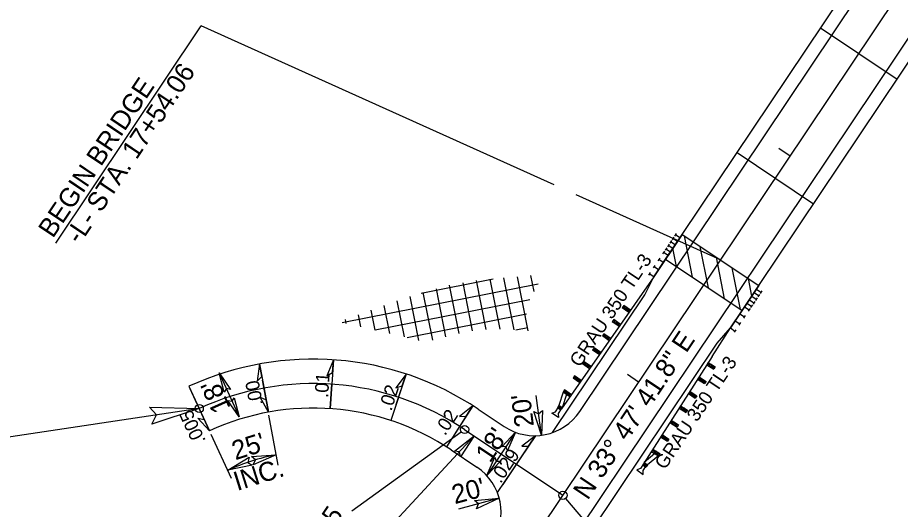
# Model space of a CAD drawing. Extents: x 1716813 to 1718091, y 800228 to 801730.
# Drawn here: x 1717290.1 to 1717614.3, y 800961.6 to 801142.3 of the extents above; entities that cross this region are included whole.
import ezdxf

# ---------------------------------------------------------------- set-up
doc = ezdxf.new("R2010")
doc.units = 0
for name, color, linetype in [('Prop Approach Slab', 7, 'Continuous'), ('Prop Dimension', 7, 'Continuous'), ('Prop Dimension Text', 7, 'Continuous'), ('Prop EOT', 7, 'Continuous'), ('Prop Guardrail', 7, 'Continuous'), ('Prop Guardrail Anchor Unit CELL', 7, 'Continuous'), ('Prop Horizontal Alignment', 7, 'Continuous'), ('Prop Horizontal Alignment Direction Label', 7, 'Continuous'), ('Prop Horizontal Alignment Station Label', 7, 'Continuous'), ('Prop Horizontal Alignment Tick Large', 7, 'Continuous'), ('Prop Horizontal Alignment Tick Small', 7, 'Continuous'), ('Prop Paved Shoulder', 7, 'Continuous'), ('Prop Rem of Exist Asph Pvmt', 7, 'Continuous'), ('Prop Roadway Bridge', 7, 'Continuous'), ('Prop Structure Anchor Unit CELL', 7, 'Continuous'), ('Prop Superelevation  Arrow CELL', 7, 'Continuous'), ('Prop Superelevation Label', 7, 'Continuous'), ('Prop Terminator CELL', 7, 'Continuous')]:
    doc.layers.add(name, color=color, linetype=linetype)

msp = doc.modelspace()

# ---------------------------------------------------------------- linework, layer by layer
at = {"layer": 'Prop Approach Slab'}
for p, q in [((1717528.05, 801053.5), (1717534.16, 801062.64)), ((1717537.95, 801046.87), (1717534.93, 801062.13)), ((1717532.07, 801050.81), (1717530.74, 801057.53)), ((1717543.82, 801042.94), (1717540.8, 801058.2)), ((1717528.05, 801053.5), (1717556.16, 801034.68)), ((1717549.7, 801039.01), (1717546.68, 801054.27)), ((1717555.58, 801035.08), (1717552.55, 801050.33)), ((1717559.7, 801039.98), (1717558.43, 801046.4)), ((1717556.16, 801034.68), (1717562.28, 801043.83))]:
    msp.add_line(p, q, dxfattribs=at)
at = {"layer": 'Prop Dimension'}
for p, q in [((1717364.14, 801011.72), (1717371.42, 800995.53)), ((1717482.44, 800988.82), (1717480.56, 801003.42)), ((1717385.77, 800977.82), (1717382.4, 800996.16)), ((1717368.63, 800972.93), (1717361.2, 800989.06)), ((1717472.9, 800989.91), (1717462.35, 800973.99)), ((1717466.92, 800965.68), (1717452.01, 800961.65))]:
    msp.add_line(p, q, dxfattribs=at)
msp.add_arc((1717398.63, 800907.81), 75, 100.4104, 114.7344, dxfattribs=at)
at = {"layer": 'Prop Dimension Text'}
for p, q in [((1717304.11, 801059.4), (1717357.55, 801139.24)), ((1717487.11, 801080.8), (1717357.55, 801139.24)), ((1717548.22, 801053.23), (1717495.17, 801077.16))]:
    msp.add_line(p, q, dxfattribs=at)
at = {"layer": 'Prop EOT'}
for p, q in [((1717496.5, 800997.53), (1717644.84, 801219.17)), ((1717458.6, 800897.76), (1717664.79, 801205.82)), ((1717459.26, 800998.39), (1717468.75, 800992.04)), ((1717449.25, 800983.43), (1717458.74, 800977.08))]:
    msp.add_line(p, q, dxfattribs=at)
for centre, radius, start, end in [((1717398.63, 800907.81), 109, 56.2051, 114.7344), ((1717398.63, 800907.81), 91, 56.2051, 114.7344), ((1717479.88, 801008.66), 20, 236.2051, 326.2051), ((1717447.62, 800960.46), 20, 326.2051, 56.2051)]:
    msp.add_arc(centre, radius, start, end, dxfattribs=at)
at = {"layer": 'Prop Guardrail'}
for p, q in [((1717523.73, 801047.06), (1717516.58, 801036.82)), ((1717545.11, 801017.72), (1717551.85, 801028.24))]:
    msp.add_line(p, q, dxfattribs=at)
at = {"layer": 'Prop Guardrail Anchor Unit CELL'}
for p, q in [((1717516.58, 801036.82), (1717489.83, 800998.47)), ((1717512.66, 801036.45), (1717512.09, 801035.63)), ((1717514.55, 801033.91), (1717512.09, 801035.63)), ((1717512.09, 801035.63), (1717513.89, 801035.59)), ((1717515.12, 801034.73), (1717512.66, 801036.45)), ((1717513.32, 801034.77), (1717512.66, 801036.45)), ((1717513.89, 801035.59), (1717513.32, 801034.77)), ((1717514.55, 801033.91), (1717513.32, 801034.77)), ((1717513.32, 801034.77), (1717515.12, 801034.73)), ((1717513.89, 801035.59), (1717514.55, 801033.91)), ((1717515.12, 801034.73), (1717514.55, 801033.91)), ((1717509.01, 801031.31), (1717508.44, 801030.49)), ((1717510.94, 801028.74), (1717508.44, 801030.49)), ((1717508.44, 801030.49), (1717510.26, 801030.43)), ((1717511.52, 801029.56), (1717509.01, 801031.31)), ((1717509.69, 801029.61), (1717509.01, 801031.31)), ((1717510.26, 801030.43), (1717509.69, 801029.61)), ((1717510.26, 801030.43), (1717510.94, 801028.74)), ((1717511.52, 801029.56), (1717509.69, 801029.61)), ((1717505.41, 801026.14), (1717504.84, 801025.32)), ((1717507.34, 801023.57), (1717504.84, 801025.32)), ((1717504.84, 801025.32), (1717506.66, 801025.27)), ((1717507.91, 801024.39), (1717505.41, 801026.14)), ((1717506.09, 801024.44), (1717505.41, 801026.14)), ((1717506.66, 801025.27), (1717506.09, 801024.44)), ((1717507.91, 801024.39), (1717506.09, 801024.44)), ((1717506.66, 801025.27), (1717507.34, 801023.57)), ((1717501.82, 801020.96), (1717501.24, 801020.14)), ((1717504.31, 801019.23), (1717501.82, 801020.96)), ((1717502.49, 801019.27), (1717501.82, 801020.96)), ((1717503.73, 801018.4), (1717501.24, 801020.14)), ((1717501.24, 801020.14), (1717503.06, 801020.09)), ((1717503.06, 801020.09), (1717502.49, 801019.27)), ((1717504.31, 801019.23), (1717502.49, 801019.27)), ((1717503.06, 801020.09), (1717503.73, 801018.4)), ((1717504.31, 801019.23), (1717503.73, 801018.4)), ((1717545.11, 801017.72), (1717519.89, 800978.35)), ((1717498.13, 801015.85), (1717497.56, 801015.03)), ((1717500.13, 801013.24), (1717497.56, 801015.03)), ((1717497.56, 801015.03), (1717499.42, 801014.95)), ((1717500.7, 801014.06), (1717498.13, 801015.85)), ((1717498.84, 801014.13), (1717498.13, 801015.85)), ((1717499.42, 801014.95), (1717498.84, 801014.13)), ((1717500.7, 801014.06), (1717498.84, 801014.13)), ((1717499.42, 801014.95), (1717500.13, 801013.24)), ((1717543.74, 801015.58), (1717543.2, 801014.74)), ((1717545, 801014.77), (1717543.2, 801014.74)), ((1717543.2, 801014.74), (1717545.72, 801013.12)), ((1717543.2, 801014.74), (1717544.46, 801013.93)), ((1717543.74, 801015.58), (1717546.26, 801013.96)), ((1717544.46, 801013.93), (1717543.74, 801015.58)), ((1717545, 801014.77), (1717544.46, 801013.93)), ((1717544.46, 801013.93), (1717546.26, 801013.96)), ((1717545.72, 801013.12), (1717545, 801014.77)), ((1717546.26, 801013.96), (1717545.72, 801013.12)), ((1717494.64, 801010.6), (1717494.06, 801009.78)), ((1717496.52, 801008.07), (1717494.06, 801009.78)), ((1717494.06, 801009.78), (1717495.87, 801009.75)), ((1717497.1, 801008.89), (1717494.64, 801010.6)), ((1717495.29, 801008.93), (1717494.64, 801010.6)), ((1717495.87, 801009.75), (1717495.29, 801008.93)), ((1717497.1, 801008.89), (1717495.29, 801008.93)), ((1717495.87, 801009.75), (1717496.52, 801008.07)), ((1717541.62, 801009.45), (1717539.8, 801009.43)), ((1717539.8, 801009.43), (1717542.37, 801007.78)), ((1717540.34, 801010.27), (1717542.91, 801008.63)), ((1717540.34, 801010.27), (1717541.08, 801008.61)), ((1717541.62, 801009.45), (1717541.08, 801008.61)), ((1717541.08, 801008.61), (1717542.91, 801008.63)), ((1717542.37, 801007.78), (1717541.62, 801009.45)), ((1717542.91, 801008.63), (1717542.37, 801007.78)), ((1717490.41, 801004.65), (1717488.89, 800999.74)), ((1717490.98, 801005.47), (1717490.41, 801004.65)), ((1717492.92, 801002.9), (1717490.41, 801004.65)), ((1717490.41, 801004.65), (1717492.23, 801004.6)), ((1717493.49, 801003.72), (1717490.98, 801005.47)), ((1717491.66, 801003.78), (1717490.98, 801005.47)), ((1717492.23, 801004.6), (1717491.66, 801003.78)), ((1717492.23, 801004.6), (1717492.92, 801002.9)), ((1717536.94, 801004.97), (1717539.5, 801003.32)), ((1717536.94, 801004.97), (1717537.68, 801003.3)), ((1717491.66, 801003.78), (1717490.12, 800998.88)), ((1717493.49, 801003.72), (1717491.66, 801003.78)), ((1717538.22, 801004.14), (1717536.4, 801004.12)), ((1717536.4, 801004.12), (1717538.96, 801002.48)), ((1717538.22, 801004.14), (1717537.68, 801003.3)), ((1717537.68, 801003.3), (1717539.5, 801003.32)), ((1717538.96, 801002.48), (1717538.22, 801004.14)), ((1717539.5, 801003.32), (1717538.96, 801002.48)), ((1717487.59, 800997.47), (1717488.74, 800999.17)), ((1717488.89, 800999.74), (1717488.31, 800998.92)), ((1717489.54, 800998.06), (1717488.31, 800998.92)), ((1717488.31, 800998.92), (1717490.12, 800998.88)), ((1717488.89, 800999.74), (1717488.6, 800999.33)), ((1717489.75, 800998.49), (1717488.61, 800996.79)), ((1717488.74, 800999.17), (1717489.24, 800998.83)), ((1717490.12, 800998.88), (1717488.89, 800999.74)), ((1717489.54, 800998.06), (1717488.89, 800999.74)), ((1717489.24, 800998.83), (1717489.75, 800998.49)), ((1717533.54, 800999.66), (1717533, 800998.82)), ((1717534.82, 800998.84), (1717533, 800998.82)), ((1717533, 800998.82), (1717535.55, 800997.18)), ((1717533.54, 800999.66), (1717536.09, 800998.02)), ((1717533.54, 800999.66), (1717534.28, 800998)), ((1717534.82, 800998.84), (1717534.28, 800998)), ((1717534.28, 800998), (1717536.09, 800998.02)), ((1717535.55, 800997.18), (1717534.82, 800998.84)), ((1717536.09, 800998.02), (1717535.55, 800997.18)), ((1717486.23, 800996.97), (1717487.59, 800997.47)), ((1717488.67, 800995.33), (1717486.23, 800996.97)), ((1717488.61, 800996.79), (1717488.67, 800995.33)), ((1717529.6, 800993.51), (1717532.24, 800991.82)), ((1717531.46, 800993.51), (1717529.6, 800993.51)), ((1717530.14, 800994.36), (1717532.78, 800992.66)), ((1717530.14, 800994.36), (1717530.92, 800992.67)), ((1717531.46, 800993.51), (1717530.92, 800992.67)), ((1717530.92, 800992.67), (1717532.78, 800992.66)), ((1717532.24, 800991.82), (1717531.46, 800993.51)), ((1717532.78, 800992.66), (1717532.24, 800991.82)), ((1717528, 800988.24), (1717526.2, 800988.21)), ((1717526.2, 800988.21), (1717528.72, 800986.59)), ((1717526.74, 800989.05), (1717529.26, 800987.43)), ((1717526.74, 800989.05), (1717527.46, 800987.4)), ((1717528, 800988.24), (1717527.46, 800987.4)), ((1717528.72, 800986.59), (1717528, 800988.24)), ((1717527.46, 800987.4), (1717529.26, 800987.43)), ((1717529.26, 800987.43), (1717528.72, 800986.59)), ((1717524.09, 800982.07), (1717520.16, 800978.78)), ((1717524.63, 800982.92), (1717522.8, 800982.9)), ((1717522.8, 800982.9), (1717525.38, 800981.25)), ((1717523.34, 800983.74), (1717525.92, 800982.09)), ((1717523.34, 800983.74), (1717524.09, 800982.07)), ((1717524.63, 800982.92), (1717524.09, 800982.07)), ((1717524.09, 800982.07), (1717525.92, 800982.09)), ((1717525.38, 800981.25), (1717524.63, 800982.92)), ((1717525.92, 800982.09), (1717525.38, 800981.25)), ((1717519.93, 800978.29), (1717518.8, 800976.58)), ((1717520.44, 800977.95), (1717519.93, 800978.29)), ((1717520.16, 800978.78), (1717521.42, 800977.97)), ((1717520.88, 800977.12), (1717520.16, 800978.78)), ((1717525.38, 800981.25), (1717521.42, 800977.97)), ((1717518.8, 800976.58), (1717517.43, 800976.08)), ((1717517.43, 800976.08), (1717519.87, 800974.45)), ((1717519.62, 800977.93), (1717521.42, 800977.97)), ((1717519.62, 800977.93), (1717520.88, 800977.12)), ((1717519.81, 800975.91), (1717520.95, 800977.61)), ((1717519.87, 800974.45), (1717519.81, 800975.91)), ((1717520.95, 800977.61), (1717520.44, 800977.95)), ((1717521.42, 800977.97), (1717520.88, 800977.12)), ((1717521.42, 800977.97), (1717521.15, 800977.55))]:
    msp.add_line(p, q, dxfattribs=at)
at = {"layer": 'Prop Horizontal Alignment'}
for p, q in [((1717404.5, 800838.5), (1717654.82, 801212.49)), ((1717454.25, 800990.91), (1717490.34, 800966.76))]:
    msp.add_line(p, q, dxfattribs=at)
msp.add_arc((1717398.63, 800907.81), 100, 56.2051, 114.7344, dxfattribs=at)
at = {"layer": 'Prop Horizontal Alignment Direction Label'}
msp.add_line((1717401.02, 800927.49), (1717457.77, 800988.56), dxfattribs=at)
at = {"layer": 'Prop Horizontal Alignment Station Label'}
for p, q in [((1717355.3, 800998.42), (1717211.72, 800976.91)), ((1717412.87, 800961.04), (1717453.03, 800990.03)), ((1717491.31, 800965.62), (1717577.75, 800864.17))]:
    msp.add_line(p, q, dxfattribs=at)
for centre in [(1717356.79, 800998.64), (1717454.25, 800990.91), (1717490.34, 800966.76)]:
    msp.add_circle(centre, 1.5, dxfattribs=at)
at = {"layer": 'Prop Horizontal Alignment Tick Large'}
msp.add_line((1717356.79, 800998.64), (1717353.44, 801005.9), dxfattribs=at)
at = {"layer": 'Prop Horizontal Alignment Tick Small'}
for p, q in [((1717573.77, 801091.41), (1717569.62, 801094.19)), ((1717518.15, 801008.31), (1717514, 801011.09)), ((1717452.45, 800992.09), (1717455.14, 800996.31))]:
    msp.add_line(p, q, dxfattribs=at)
at = {"layer": 'Prop Paved Shoulder'}
for p, q in [((1717523.73, 801047.06), (1717528.05, 801053.5)), ((1717520.42, 801040.46), (1717523.73, 801047.06)), ((1717486.5, 800989.78), (1717520.42, 801040.46)), ((1717551.85, 801028.24), (1717556.16, 801034.68)), ((1717547.01, 801022.66), (1717551.85, 801028.24)), ((1717461.92, 800895.53), (1717547.01, 801022.66))]:
    msp.add_line(p, q, dxfattribs=at)
at = {"layer": 'Prop Rem of Exist Asph Pvmt'}
for p, q in [((1717472.38, 801027.57), (1717468.6, 801046.66)), ((1717477.54, 801027.23), (1717473.61, 801047.07)), ((1717479.77, 801041.71), (1717478.61, 801047.57)), ((1717409.32, 801030.23), (1717481.29, 801044.48)), ((1717438.29, 801041.06), (1717464.74, 801046.3)), ((1717452.25, 801026.27), (1717448.75, 801043.94)), ((1717457.17, 801027.16), (1717453.66, 801044.89)), ((1717462.15, 801027.74), (1717458.61, 801045.64)), ((1717467.24, 801027.76), (1717463.6, 801046.18)), ((1717442.55, 801023.77), (1717439.07, 801041.31)), ((1717447.4, 801025.02), (1717443.91, 801042.63)), ((1717421.42, 801027.52), (1717478.15, 801038.76)), ((1717432.11, 801024.99), (1717429.49, 801038.22)), ((1717437.48, 801023.62), (1717434.28, 801039.77)), ((1717421.43, 801027.44), (1717419.97, 801034.81)), ((1717426.77, 801026.21), (1717424.73, 801036.51)), ((1717433.15, 801024.75), (1717476.95, 801033.43)), ((1717410.75, 801029.9), (1717410.47, 801031.33)), ((1717416.09, 801028.67), (1717415.22, 801033.09)), ((1717472.99, 801027.55), (1717477.47, 801028.43))]:
    msp.add_line(p, q, dxfattribs=at)
at = {"layer": 'Prop Roadway Bridge'}
for p, q in [((1717534.16, 801062.64), (1717602.3, 801164.45)), ((1717562.28, 801043.83), (1717630.42, 801145.63)), ((1717584.96, 801138.53), (1717613.07, 801119.72)), ((1717554.29, 801092.72), (1717582.41, 801073.9)), ((1717534.16, 801062.64), (1717562.28, 801043.83))]:
    msp.add_line(p, q, dxfattribs=at)
at = {"layer": 'Prop Structure Anchor Unit CELL'}
for p, q in [((1717534.16, 801062.64), (1717523.73, 801047.06)), ((1717531.95, 801062.93), (1717531.31, 801061.98)), ((1717530.21, 801060.34), (1717529.58, 801059.39)), ((1717531.56, 801058.75), (1717529.89, 801059.86)), ((1717531.08, 801061.64), (1717530.44, 801060.68)), ((1717532.43, 801060.05), (1717530.76, 801061.16)), ((1717533.29, 801061.35), (1717531.63, 801062.46)), ((1717527.61, 801056.44), (1717526.97, 801055.49)), ((1717528.47, 801057.74), (1717527.84, 801056.79)), ((1717529.82, 801056.15), (1717528.16, 801057.26)), ((1717529.34, 801059.04), (1717528.71, 801058.09)), ((1717530.69, 801057.45), (1717529.03, 801058.56)), ((1717525.87, 801053.84), (1717525.23, 801052.89)), ((1717527.21, 801052.26), (1717525.55, 801053.37)), ((1717528.95, 801054.85), (1717527.29, 801055.97)), ((1717524.13, 801051.25), (1717523.49, 801050.3)), ((1717525.47, 801049.66), (1717523.81, 801050.77)), ((1717522.39, 801048.65), (1717521.75, 801047.7)), ((1717523.73, 801047.06), (1717522.07, 801048.17)), ((1717562.28, 801043.83), (1717551.85, 801028.24)), ((1717559.67, 801039.93), (1717561.34, 801038.82)), ((1717560.54, 801041.23), (1717562.2, 801040.12)), ((1717561.41, 801042.53), (1717563.07, 801041.41)), ((1717562.52, 801040.59), (1717561.89, 801039.64)), ((1717563.39, 801041.89), (1717562.75, 801040.94)), ((1717557.93, 801037.33), (1717559.6, 801036.22)), ((1717558.8, 801038.63), (1717560.47, 801037.52)), ((1717559.92, 801036.7), (1717559.28, 801035.74)), ((1717560.78, 801037.99), (1717560.15, 801037.04)), ((1717561.65, 801039.29), (1717561.02, 801038.34)), ((1717555.33, 801033.44), (1717556.99, 801032.32)), ((1717557.07, 801036.03), (1717558.73, 801034.92)), ((1717559.05, 801035.4), (1717558.41, 801034.45)), ((1717553.59, 801030.84), (1717555.25, 801029.73)), ((1717555.57, 801030.2), (1717554.93, 801029.25)), ((1717557.31, 801032.8), (1717556.67, 801031.85)), ((1717551.85, 801028.24), (1717553.51, 801027.13)), ((1717553.83, 801027.61), (1717553.19, 801026.65))]:
    msp.add_line(p, q, dxfattribs=at)
at = {"layer": 'Prop Superelevation  Arrow CELL'}
for p, q in [((1717378.93, 801015.02), (1717381.1, 801003.21)), ((1717406.07, 801016.56), (1717405.45, 801007.58)), ((1717432.74, 801011.33), (1717428.99, 800999.94)), ((1717382.19, 800997.31), (1717380.02, 801009.11)), ((1717404.84, 800998.6), (1717405.45, 801007.58)), ((1717360.55, 800990.46), (1717355.53, 801001.36)), ((1717457.29, 800999.68), (1717450.83, 800989.56)), ((1717480.24, 800988.66), (1717473.56, 800978.69)), ((1717478.24, 800985.68), (1717468.23, 800970.73))]:
    msp.add_line(p, q, dxfattribs=at)
for points in [[(1717378.93, 801015.02), (1717378.05, 801008.75), (1717379.77, 801010.47)], [(1717406.07, 801016.56), (1717403.66, 801010.71), (1717405.75, 801011.94)], [(1717432.74, 801011.33), (1717428.96, 801006.26), (1717431.29, 801006.94)], [(1717382.19, 800997.31), (1717379.13, 801002.85), (1717381.35, 801001.86)], [(1717457.29, 800999.68), (1717452.38, 800995.7), (1717454.8, 800995.78)], [(1717360.55, 800990.46), (1717356.23, 800995.07), (1717358.62, 800994.66)], [(1717480.24, 800988.66), (1717475.24, 800984.79), (1717477.66, 800984.82)]]:
    msp.add_lwpolyline(points, close=True, dxfattribs=at)
at = {"layer": 'Prop Superelevation Label'}
for p, q in [((1717378.93, 801015.02), (1717382.19, 800997.31)), ((1717432.74, 801011.33), (1717427.11, 800994.24)), ((1717405.45, 801007.58), (1717404.84, 800998.6)), ((1717353.02, 801006.81), (1717360.55, 800990.46)), ((1717457.29, 800999.68), (1717447.61, 800984.51)), ((1717360.55, 800990.46), (1717360.55, 800990.46)), ((1717480.24, 800988.66), (1717466.24, 800967.75))]:
    msp.add_line(p, q, dxfattribs=at)
at = {"layer": 'Prop Terminator CELL'}
for points in [[(1717365.97, 801004.64), (1717364.14, 801011.72), (1717368.28, 801005.64), (1717366.74, 801005.95)], [(1717369.6, 801002.61), (1717371.42, 800995.53), (1717367.29, 801001.61), (1717368.83, 801001.3)], [(1717338.53, 800999.12), (1717356.79, 800998.64), (1717339.34, 800992.87), (1717341.15, 800996.36)], [(1717482.83, 800997.95), (1717482.44, 800988.82), (1717479.7, 800997.59), (1717481.43, 800996.66)], [(1717450.51, 800983.02), (1717457.77, 800988.56), (1717452.78, 800980.84), (1717452.39, 800982.77)], [(1717467.89, 800984.6), (1717472.9, 800989.91), (1717469.97, 800983.17), (1717469.41, 800984.65)], [(1717375.96, 800980.98), (1717385.08, 800981.58), (1717376.65, 800977.91), (1717377.39, 800979.73)], [(1717376.19, 800977.81), (1717367.25, 800975.93), (1717375.07, 800980.75), (1717374.59, 800978.84)], [(1717467.36, 800979.3), (1717462.35, 800973.99), (1717465.28, 800980.73), (1717465.84, 800979.26)], [(1717457.83, 800964.83), (1717466.92, 800965.68), (1717458.61, 800961.77), (1717459.3, 800963.62)]]:
    msp.add_lwpolyline(points, close=True, dxfattribs=at)

# ---------------------------------------------------------------- texts
at = {"layer": 'Prop Dimension'}
for s, rotation, p in [("18'", 114.2302, (1717368.42, 800998.89)), ("20'", 97.3693, (1717479.73, 800992.24)), ("18'", 56.4773, (1717463.59, 800978.32)), ("25'", 17.5724, (1717370.06, 800979.62)), ('INC.', 17.5724, (1717370.71, 800968.32)), ("20'", 15.1414, (1717450.62, 800963.46))]:
    msp.add_text(s, height=7, rotation=rotation, dxfattribs=at).set_placement(p)
at = {"layer": 'Prop Dimension Text'}
for s, p in [('-L- STA. 17+54.06', (1717312.9, 801058.69)), ('BEGIN BRIDGE', (1717303.04, 801060.94))]:
    msp.add_text(s, height=7, rotation=56.2051, dxfattribs=at).set_placement(p)
at = {"layer": 'Prop Guardrail Anchor Unit CELL'}
for p in [(1717496.57, 801013.51), (1717527.81, 800975.87)]:
    msp.add_text('GRAU 350 TL-3', height=5, rotation=56.2051, dxfattribs=at).set_placement(p)
at = {"layer": 'Prop Horizontal Alignment Direction Label'}
msp.add_text('N 33%%d 47\' 41.8" E', height=7, rotation=56.2051, dxfattribs=at).set_placement((1717499.45, 800964.69))
at = {"layer": 'Prop Horizontal Alignment Station Label'}
msp.add_text('-DRV- PT Sta.  11+02.15', height=7, rotation=56.2051, dxfattribs=at).set_placement((1717351.97, 800872.99))
at = {"layer": 'Prop Superelevation Label'}
for s, rotation, p in [('.01', 86.0865, (1717404.09, 801002.45)), ('.00', 100.4104, (1717380.23, 801000.18)), ('.02', 71.7625, (1717427.31, 800997.5)), ('.005', 114.7344, (1717359.29, 800986.84)), ('.02', 57.4386, (1717447.08, 800988.41)), ('.029', 56.2051, (1717467.47, 800970.86))]:
    msp.add_text(s, height=5, rotation=rotation, dxfattribs=at).set_placement(p)

doc.saveas('drawing.dxf')
